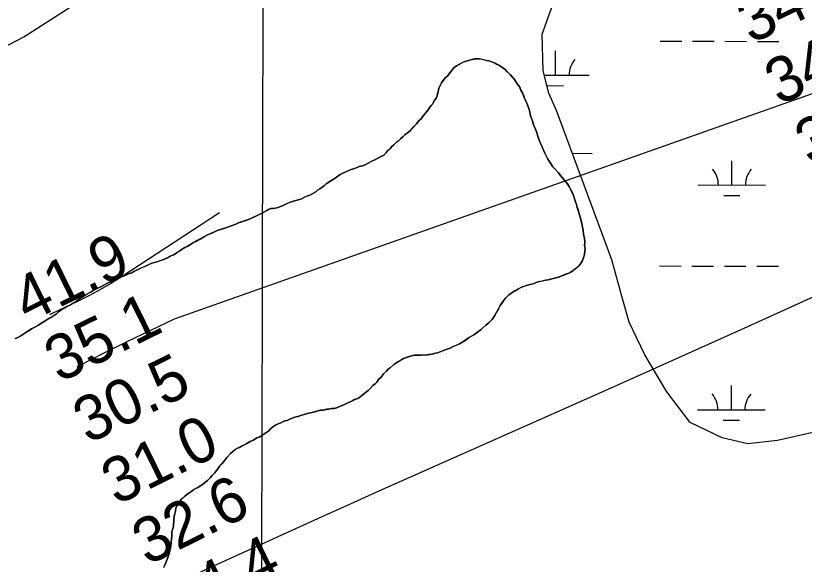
# Model space of a CAD drawing. Extents: x 3177385 to 3215275, y 903885 to 929304.
# Drawn here: x 3191697 to 3192865, y 914485 to 915297 of the extents above; entities that cross this region are included whole.
import ezdxf

# ---------------------------------------------------------------- set-up
doc = ezdxf.new("R2010")
doc.units = 0
for name, color, linetype in [('V-BORW-LINE', 7, 'Continuous'), ('V-GRID-MAJR', 7, 'Continuous'), ('V-RIVR-RANG', 7, 'Continuous'), ('V-SITE-VEGE', 7, 'Continuous'), ('V-TOPO-MAJR', 7, 'Continuous'), ('V-TOPO-MINR', 7, 'Continuous'), ('V-TOPO-SHOR', 7, 'Continuous'), ('V-WETL-SWMP', 7, 'Continuous')]:
    doc.layers.add(name, color=color, linetype=linetype)

msp = doc.modelspace()

# ---------------------------------------------------------------- linework, layer by layer
at = {"layer": 'V-BORW-LINE'}
for points in [[(3191709.1, 915265.3), (3191863.4, 915364.4)], [(3191587.4, 915201.6), (3191709.1, 915265.3)]]:
    msp.add_lwpolyline(points, dxfattribs=at)
at = {"layer": 'V-GRID-MAJR'}
msp.add_spline([(3192048.7, 909312.8), (3192063.7, 915372.6), (3192078.7, 921435.5), (3192093.7, 927498.5), (3192093.7, 927501.6)], degree=3, dxfattribs=at)
at = {"layer": 'V-SITE-VEGE'}
for points in [[(3192531.7, 914926.9), (3192534.5, 914931), (3192536, 914933.6), (3192538.5, 914940.1), (3192539.3, 914943.9), (3192540.3, 914952.6), (3192539.6, 914956.4), (3192539.7, 914961.4), (3192539.4, 914967.1), (3192538, 914973.2), (3192537.4, 914979.4), (3192536.3, 914983.6), (3192535.3, 914989.3), (3192532.5, 915000.4), (3192530.7, 915006.9), (3192528.2, 915014.2), (3192527.5, 915017.3), (3192526.1, 915021.5), (3192523.2, 915030.7), (3192519.2, 915039.2), (3192516.7, 915043.8), (3192512.2, 915050.4), (3192506.3, 915057.4), (3192503.3, 915060.5), (3192500.7, 915064), (3192495.5, 915070.2), (3192492.5, 915073.3), (3192489.9, 915076.8), (3192485.1, 915084.5), (3192480.4, 915093.4), (3192476, 915103.8), (3192473.1, 915110.3), (3192471.3, 915115.3), (3192467.7, 915126.4), (3192465.9, 915131), (3192464.1, 915135.3), (3192463.1, 915139.5), (3192459.4, 915148.7), (3192458.4, 915154.5), (3192457, 915159.4), (3192454.8, 915164.8), (3192452.3, 915170.6), (3192450.5, 915174.4), (3192447.9, 915181.4), (3192444.6, 915187.5), (3192443.6, 915191), (3192439.9, 915196), (3192435.8, 915202.2), (3192432.5, 915206.1), (3192429.1, 915209.6), (3192424.3, 915214.3), (3192422, 915217), (3192417.1, 915220.5), (3192413.4, 915222.9), (3192405.9, 915227.2), (3192397.9, 915230.1), (3192394.5, 915230.5), (3192383.9, 915233), (3192379.7, 915233.1), (3192376.6, 915232.8), (3192370.5, 915231.4), (3192366.3, 915230), (3192362.4, 915228.9), (3192358.6, 915227.5), (3192353.2, 915224.5), (3192349.7, 915222.3), (3192346.6, 915220.1), (3192343.9, 915217.1), (3192336.4, 915207.4), (3192333.7, 915205.5), (3192331.8, 915202.9), (3192327.8, 915197.3), (3192325.5, 915193.5), (3192324.3, 915190.5), (3192323.1, 915187.1), (3192322.6, 915184), (3192321, 915178), (3192319.7, 915174.9), (3192317.8, 915172.3), (3192314.6, 915167), (3192314.2, 915165.9), (3192312.7, 915164.4), (3192310.3, 915161.4), (3192308.7, 915158.8), (3192306.4, 915155.4), (3192304, 915152.4), (3192300.5, 915148.3), (3192297.4, 915144.2), (3192295, 915141.9), (3192292.3, 915138.9), (3192290.3, 915136.3), (3192281.8, 915127), (3192278.7, 915124.4), (3192275.9, 915122.5), (3192273.2, 915120.3), (3192270.9, 915118), (3192267, 915114.7), (3192264.3, 915112.1), (3192261.6, 915110.2), (3192256.9, 915105.4), (3192254.2, 915103.2)], [(3192254.2, 915103.2), (3192251.9, 915100.9), (3192242.1, 915090.5), (3192237.1, 915087.9), (3192233.2, 915086.1), (3192229.8, 915083.9), (3192224.4, 915081.3), (3192214.7, 915076.2), (3192210.9, 915074.7), (3192205.9, 915073.7), (3192202.8, 915072.2), (3192197.1, 915070.1), (3192192.5, 915068.6), (3192184.8, 915065.4), (3192181.7, 915063.5), (3192177.8, 915061.7), (3192172.4, 915058), (3192168.9, 915055.4), (3192166.2, 915053.6), (3192162.4, 915051.4), (3192157, 915047.7), (3192154.2, 915045.4), (3192147.3, 915040.3), (3192144.2, 915038.4), (3192141.5, 915036.2), (3192137.2, 915033.6), (3192132.6, 915031), (3192129.5, 915030.3), (3192124.9, 915028.2), (3192119.5, 915025.2), (3192115.3, 915024.2), (3192103.8, 915020.6), (3192096.1, 915017.3), (3192093.4, 915015.9), (3192089.2, 915014.4), (3192085.7, 915013), (3192081.5, 915011.9), (3192075, 915011.3), (3192071.7, 915010), (3192068.9, 915008.3)], [(3192068.9, 915008.3), (3192060.9, 915004.2), (3192057.7, 915002.4), (3192044.1, 914996.1), (3192034.7, 914992.6), (3192026.9, 914990), (3192023.1, 914988.2), (3192016.4, 914985.6), (3192012.3, 914984.4), (3192008.4, 914983), (3191997.1, 914979.4), (3191993.6, 914977.9), (3191985, 914974.1), (3191981.3, 914972.2), (3191960.6, 914960.9), (3191957.6, 914959.1), (3191953.7, 914956.4), (3191950.9, 914955), (3191947.5, 914953.6), (3191942.7, 914950.5), (3191939.9, 914948.4), (3191930.6, 914942.6), (3191926.1, 914941), (3191922.8, 914938.9), (3191913.6, 914934.7), (3191906.3, 914932.7), (3191902.9, 914931.5), (3191898.6, 914930.3), (3191894.3, 914928.7), (3191888.4, 914925.8), (3191881.6, 914922.8), (3191878.3, 914920.9), (3191875.3, 914919.5), (3191872.3, 914918.3), (3191869.1, 914916.4), (3191865.2, 914915), (3191861.1, 914913), (3191857.9, 914911.7), (3191850.3, 914908.5), (3191846.9, 914906.9), (3191841.7, 914904.2), (3191835.3, 914901.8), (3191832, 914900.3), (3191827.5, 914897.9), (3191823, 914895.6), (3191820, 914894), (3191812, 914890.1), (3191809, 914888.3), (3191800.1, 914883.3), (3191795.6, 914880), (3191792.3, 914878), (3191789.9, 914876.1), (3191785, 914872.8), (3191781.3, 914870.9), (3191778.5, 914868.9), (3191773.1, 914866.2), (3191766.8, 914862.9), (3191764, 914861.1), (3191760.6, 914858.6), (3191757.5, 914855.7), (3191749.5, 914850.3), (3191746.3, 914848.7), (3191742.2, 914846.2), (3191739.3, 914844.1), (3191734.6, 914841.2), (3191730.9, 914838.7), (3191724.7, 914835.5), (3191720.8, 914833.2), (3191712.1, 914827.8), (3191709.1, 914825.8), (3191704.6, 914823.1), (3191699.4, 914820.2), (3191696.2, 914818.8)], [(3192028.6, 914657.8), (3192031.7, 914659.7), (3192034.8, 914661.1), (3192039.4, 914663.7), (3192044.4, 914666.7), (3192049, 914668.5), (3192054.4, 914671.8), (3192057.5, 914673.2), (3192061.4, 914675.4), (3192064.5, 914677.3), (3192071.8, 914682.5), (3192074.5, 914685.5), (3192077.7, 914688.1), (3192081.9, 914690.6), (3192085.8, 914692.5), (3192088.8, 914693.5), (3192091.9, 914695.4), (3192095.8, 914697.2), (3192099.2, 914697.9), (3192104.2, 914700.1), (3192110.7, 914702.6), (3192115, 914703.6), (3192119.2, 914705.1), (3192125.7, 914706.9), (3192131.1, 914708.6), (3192136, 914709.7), (3192148.7, 914712.8), (3192152.5, 914713.1), (3192165.5, 914715.5), (3192169.3, 914715.5), (3192173.5, 914716.9), (3192178.9, 914719.4), (3192183.2, 914720.9), (3192187.8, 914723.1), (3192193.2, 914726), (3192196.3, 914727.1), (3192199, 914728.5), (3192203.9, 914730.3), (3192209.4, 914734), (3192214.4, 914738.5), (3192219.1, 914742.2), (3192221.8, 914744.8), (3192226.1, 914749.3), (3192229.6, 914751.9), (3192231.9, 914754.5), (3192234.6, 914758.3), (3192238.2, 914762), (3192241.7, 914766.5), (3192246, 914770.6), (3192248.7, 914773.6), (3192251.4, 914775.4), (3192257.2, 914780.3), (3192263, 914784.3), (3192271.5, 914789.5), (3192281.5, 914792.7), (3192287.6, 914794.1), (3192292.6, 914794.4), (3192297.5, 914794.3), (3192300.6, 914794.6), (3192304, 914794.5), (3192314, 914795.8), (3192317, 914796.9), (3192321.6, 914798), (3192325.5, 914799.4), (3192330.8, 914801.2), (3192335.8, 914803), (3192340.4, 914804.8), (3192345.1, 914807), (3192354.3, 914811), (3192364.3, 914817.2), (3192367.8, 914819.8), (3192375.6, 914824.6), (3192381, 914828.3), (3192386.4, 914832.4), (3192388.7, 914834.6), (3192393.4, 914838.7), (3192398.8, 914843.2), (3192402.7, 914847.3), (3192404.7, 914850.3), (3192407.1, 914854.1), (3192411.8, 914863.1), (3192414.6, 914867.6), (3192420.1, 914875.9), (3192422.4, 914878.5), (3192427.1, 914883.4), (3192432.1, 914887.1), (3192440.6, 914892.2), (3192446, 914894.8), (3192454.9, 914898), (3192458.7, 914899.1), (3192463.3, 914900.1), (3192466.8, 914901.2), (3192470.2, 914902.7), (3192481.7, 914905.1), (3192485.5, 914905.8), (3192495.1, 914908.2), (3192500.9, 914910), (3192516.2, 914915.8), (3192519.3, 914917.2), (3192522.4, 914919.5), (3192531.7, 914926.9)], [(3191916.6, 914480), (3191920.2, 914488.3), (3191923.8, 914499.2), (3191925.1, 914503), (3191925.9, 914506.8), (3191927.1, 914511), (3191927.3, 914517.5), (3191927.8, 914522.8), (3191928.2, 914526.6), (3191928.4, 914532.7), (3191929.6, 914537.6), (3191930.8, 914541.4), (3191931.4, 914550.5), (3191931.9, 914555.9), (3191933.6, 914563.4), (3191934.5, 914568.4), (3191936.1, 914571.8), (3191937.6, 914574.4), (3191940, 914577.4), (3191942.7, 914581.2), (3191947.4, 914585.6), (3191950.5, 914588.2), (3191956.3, 914592.3), (3191961, 914595.3), (3191967.1, 914598.6), (3191970.6, 914601.2), (3191973.7, 914603), (3191976.8, 914605.2), (3191981.4, 914608.9), (3191985, 914613), (3191988.1, 914616.4), (3191991.6, 914619.8), (3191994.3, 914623.5), (3191996.7, 914626.1), (3191998.6, 914629.1), (3192005.3, 914637), (3192009.6, 914643), (3192015.4, 914648.6), (3192018.9, 914651.6), (3192022.1, 914654.6), (3192025.5, 914656.8), (3192028.6, 914657.8)]]:
    msp.add_lwpolyline(points, dxfattribs=at)
at = {"layer": 'V-TOPO-MAJR'}
msp.add_lwpolyline([(3191998.7, 915005.2), (3191854.9, 914910.9), (3191839, 914901), (3191822.9, 914891.5), (3191806.4, 914882.6), (3191789.6, 914874.2), (3191751.1, 914855.8), (3191747.4, 914854.1)], dxfattribs=at)
at = {"layer": 'V-TOPO-MINR'}
for points in [[(3193910, 915545.9), (3193851.2, 915525.6), (3193792.7, 915504.9), (3193770.2, 915496.8), (3193700.5, 915471.5), (3193630.9, 915446.1), (3193561.3, 915420.5), (3193491.8, 915394.9), (3193380, 915353.4), (3193307.5, 915326.9), (3193234.9, 915301.1), (3193161.9, 915276), (3193088.8, 915251.4), (3192986.9, 915217.8), (3192964.6, 915210.7), (3192942.1, 915204.1), (3191931.7, 914847.6), (3191896.6, 914830.9), (3191861.6, 914813.9), (3191826.7, 914796.6), (3191792, 914779), (3191787.8, 914776.8)], [(3191639.2, 914323.2), (3191734.4, 914366.2), (3191829.6, 914409.4), (3191948.7, 914463.5), (3191984.3, 914479.6), (3192019.9, 914495.8), (3192055.5, 914512.1), (3192091.2, 914528.3), (3192106.5, 914535.2), (3192149.8, 914554.9), (3192193.1, 914574.4), (3192236.5, 914593.9), (3192279.9, 914613.2), (3192451.1, 914689.2), (3192533.6, 914725.9), (3192616.2, 914762.8), (3192698.6, 914799.8), (3192781.1, 914836.9), (3192889.7, 914885.9)]]:
    msp.add_lwpolyline(points, dxfattribs=at)
at = {"layer": 'V-TOPO-SHOR'}
for points in [[(3192075, 915011.3), (3192078.4, 915011.6), (3192081.5, 915011.9), (3192085.7, 915013), (3192089.2, 915014.4), (3192093.4, 915015.9), (3192096.1, 915017.3), (3192100.3, 915019.2), (3192103.8, 915020.6), (3192107.2, 915021.7), (3192111.8, 915023.1), (3192115.3, 915024.2), (3192119.5, 915025.2), (3192124.9, 915028.2), (3192129.5, 915030.3), (3192132.6, 915031), (3192137.2, 915033.6), (3192141.5, 915036.2), (3192144.2, 915038.4), (3192147.3, 915040.3), (3192154.2, 915045.4), (3192157, 915047.7), (3192162.4, 915051.4), (3192166.2, 915053.6), (3192168.9, 915055.4), (3192172.4, 915058), (3192177.8, 915061.7), (3192181.7, 915063.5), (3192184.8, 915065.4), (3192188.2, 915066.8), (3192192.5, 915068.6), (3192197.1, 915070.1), (3192202.8, 915072.2), (3192205.9, 915073.7), (3192210.9, 915074.7), (3192214.7, 915076.2), (3192219, 915078.4), (3192224.4, 915081.3), (3192229.8, 915083.9), (3192233.2, 915086.1), (3192237.1, 915087.9), (3192242.1, 915090.5), (3192246, 915094.6), (3192248.3, 915097.2), (3192251.9, 915100.9), (3192254.2, 915103.2), (3192256.9, 915105.4), (3192261.6, 915110.2), (3192264.3, 915112.1), (3192267, 915114.7), (3192270.9, 915118), (3192273.2, 915120.3), (3192275.9, 915122.5), (3192278.7, 915124.4), (3192281.8, 915127), (3192284.1, 915129.6), (3192286.8, 915132.6), (3192290.3, 915136.3), (3192292.3, 915138.9), (3192295, 915141.9), (3192297.4, 915144.2), (3192300.5, 915148.3), (3192304, 915152.4), (3192306.4, 915155.4), (3192308.7, 915158.8), (3192310.3, 915161.4), (3192312.7, 915164.4), (3192314.2, 915165.9), (3192314.6, 915167), (3192316.2, 915169.7), (3192317.8, 915172.3), (3192319.7, 915174.9), (3192321, 915178), (3192321.8, 915181), (3192322.6, 915184), (3192323.1, 915187.1), (3192324.3, 915190.5), (3192325.5, 915193.5), (3192327.8, 915197.3), (3192331.8, 915202.9), (3192333.7, 915205.5), (3192336.4, 915207.4), (3192339.6, 915211.5), (3192341.9, 915214.5), (3192343.9, 915217.1), (3192346.6, 915220.1), (3192349.7, 915222.3), (3192353.2, 915224.5), (3192355.9, 915226), (3192358.6, 915227.5), (3192362.4, 915228.9), (3192366.3, 915230), (3192370.5, 915231.4), (3192373.6, 915232.1), (3192376.6, 915232.8), (3192379.7, 915233.1), (3192383.9, 915233), (3192387.3, 915232.2), (3192391.1, 915231.3), (3192394.5, 915230.5), (3192397.9, 915230.1)], [(3192397.9, 915230.1), (3192402.4, 915228.4), (3192405.9, 915227.2), (3192409.2, 915225.2), (3192413.4, 915222.9), (3192417.1, 915220.5), (3192422, 915217), (3192424.3, 915214.3), (3192429.1, 915209.6), (3192432.5, 915206.1), (3192435.8, 915202.2), (3192439.9, 915196), (3192443.6, 915191), (3192444.6, 915187.5), (3192447.9, 915181.4), (3192449.4, 915177.5), (3192450.5, 915174.4), (3192452.3, 915170.6), (3192454.8, 915164.8), (3192457, 915159.4), (3192458.4, 915154.5), (3192459.4, 915148.7), (3192463.1, 915139.5), (3192464.1, 915135.3), (3192465.9, 915131), (3192467.7, 915126.4), (3192471.3, 915115.3), (3192473.1, 915110.3), (3192476, 915103.8), (3192478.6, 915097.6), (3192480.4, 915093.4), (3192481.8, 915090.7), (3192485.1, 915084.5), (3192489.9, 915076.8), (3192492.5, 915073.3), (3192495.5, 915070.2), (3192500.7, 915064), (3192503.3, 915060.5), (3192506.3, 915057.4), (3192509.3, 915053.9), (3192512.2, 915050.4), (3192514.1, 915047.7), (3192516.7, 915043.8), (3192519.2, 915039.2), (3192521.4, 915034.6), (3192523.2, 915030.7), (3192524.3, 915027.3), (3192526.1, 915021.5), (3192527.5, 915017.3), (3192528.2, 915014.2), (3192529.3, 915011.2), (3192530.7, 915006.9), (3192532.5, 915000.4), (3192534.3, 914993.5), (3192535.3, 914989.3), (3192536.3, 914983.6), (3192537.4, 914979.4), (3192538, 914973.2), (3192539.4, 914967.1), (3192539.7, 914961.4), (3192539.6, 914956.4), (3192540.3, 914952.6), (3192539.8, 914947.7), (3192539.3, 914943.9), (3192538.5, 914940.1), (3192536, 914933.6), (3192534.5, 914931), (3192531.7, 914926.9), (3192527.1, 914923.2), (3192522.4, 914919.5), (3192519.3, 914917.2), (3192516.2, 914915.8), (3192510.5, 914913.6), (3192500.9, 914910), (3192495.1, 914908.2), (3192490.9, 914907.2), (3192485.5, 914905.8), (3192481.7, 914905.1), (3192476.7, 914904), (3192470.2, 914902.7), (3192466.8, 914901.2), (3192463.3, 914900.1), (3192458.7, 914899.1), (3192454.9, 914898), (3192451, 914896.6), (3192446, 914894.8), (3192440.6, 914892.2), (3192436.4, 914889.7), (3192432.1, 914887.1), (3192427.1, 914883.4), (3192422.4, 914878.5), (3192420.1, 914875.9), (3192417.3, 914871.8), (3192414.6, 914867.6), (3192411.8, 914863.1), (3192408.6, 914857.1), (3192407.1, 914854.1), (3192404.7, 914850.3), (3192402.7, 914847.3), (3192398.8, 914843.2), (3192393.4, 914838.7)], [(3191985, 914974.1), (3191989.5, 914976.1), (3191993.6, 914977.9), (3191997.1, 914979.4), (3192002, 914981), (3192005.2, 914982), (3192008.4, 914983), (3192012.3, 914984.4), (3192016.4, 914985.6), (3192023.1, 914988.2), (3192026.9, 914990), (3192030.4, 914991.2), (3192034.7, 914992.6), (3192039.2, 914994.2), (3192044.1, 914996.1), (3192047.1, 914997.5), (3192051.5, 914999.5), (3192054.7, 915001), (3192057.7, 915002.4), (3192060.9, 915004.2), (3192063.7, 915005.7), (3192068.9, 915008.3), (3192071.7, 915010), (3192075, 915011.3)], [(3191696.2, 914818.8), (3191699.4, 914820.2), (3191704.6, 914823.1), (3191709.1, 914825.8), (3191712.1, 914827.8), (3191715.8, 914830.1), (3191720.8, 914833.2), (3191724.7, 914835.5), (3191730.9, 914838.7), (3191734.6, 914841.2), (3191739.3, 914844.1), (3191742.2, 914846.2), (3191746.3, 914848.7), (3191749.5, 914850.3), (3191752.5, 914852.4), (3191757.5, 914855.7), (3191760.6, 914858.6), (3191764, 914861.1), (3191766.8, 914862.9), (3191770.1, 914864.6), (3191773.1, 914866.2), (3191778.5, 914868.9), (3191781.3, 914870.9), (3191785, 914872.8), (3191789.9, 914876.1), (3191792.3, 914878), (3191795.6, 914880), (3191800.1, 914883.3), (3191804.2, 914885.6), (3191809, 914888.3), (3191812, 914890.1), (3191820, 914894), (3191823, 914895.6), (3191827.5, 914897.9), (3191832, 914900.3), (3191835.3, 914901.8), (3191838.5, 914903), (3191841.7, 914904.2), (3191846.9, 914906.9), (3191850.3, 914908.5), (3191854, 914910.1), (3191857.9, 914911.7), (3191861.1, 914913), (3191865.2, 914915), (3191869.1, 914916.4), (3191872.3, 914918.3), (3191875.3, 914919.5), (3191878.3, 914920.9), (3191881.6, 914922.8), (3191885.2, 914924.4), (3191888.4, 914925.8), (3191891.5, 914927.2), (3191894.3, 914928.7), (3191898.6, 914930.3), (3191902.9, 914931.5), (3191906.3, 914932.7), (3191909.9, 914933.7), (3191913.6, 914934.7), (3191917.5, 914936.5), (3191922.8, 914938.9), (3191926.1, 914941), (3191930.6, 914942.6), (3191936.2, 914946.1), (3191939.9, 914948.4), (3191942.7, 914950.5), (3191947.5, 914953.6), (3191950.9, 914955), (3191953.7, 914956.4), (3191957.6, 914959.1), (3191960.6, 914960.9), (3191963.7, 914962.6), (3191966.7, 914964.2), (3191970.1, 914966.1), (3191976.8, 914969.8), (3191981.3, 914972.2), (3191985, 914974.1)], [(3192393.4, 914838.7), (3192388.7, 914834.6), (3192386.4, 914832.4), (3192381, 914828.3), (3192375.6, 914824.6), (3192372.1, 914822.4), (3192367.8, 914819.8), (3192364.3, 914817.3), (3192360.1, 914814.7), (3192354.3, 914811), (3192349.3, 914808.8), (3192345.1, 914807), (3192340.4, 914804.8), (3192335.8, 914803), (3192330.8, 914801.2), (3192325.5, 914799.4), (3192321.6, 914798), (3192317, 914796.9), (3192314, 914795.8), (3192309, 914795.2), (3192304, 914794.5), (3192300.6, 914794.6), (3192297.5, 914794.3), (3192292.6, 914794.4), (3192287.6, 914794.1), (3192281.5, 914792.7), (3192276.9, 914791.3), (3192271.5, 914789.5), (3192267.3, 914786.9), (3192263, 914784.3), (3192257.2, 914780.3), (3192251.4, 914775.4), (3192248.7, 914773.6), (3192246, 914770.6), (3192241.7, 914766.5), (3192238.2, 914762), (3192234.6, 914758.3), (3192231.9, 914754.5), (3192229.6, 914751.9), (3192226.1, 914749.3), (3192221.8, 914744.8), (3192219.1, 914742.2), (3192214.4, 914738.5), (3192209.4, 914734), (3192206.7, 914732.2), (3192203.9, 914730.3), (3192199, 914728.5), (3192196.3, 914727.1), (3192193.2, 914726), (3192187.8, 914723.1), (3192183.2, 914720.9), (3192178.9, 914719.4), (3192173.5, 914716.9), (3192169.3, 914715.5), (3192165.5, 914715.5), (3192162.1, 914714.8), (3192157.9, 914714.2), (3192152.5, 914713.1), (3192148.7, 914712.8), (3192144.5, 914711.8), (3192136, 914709.7), (3192131.1, 914708.6), (3192125.7, 914706.9), (3192119.2, 914705.1), (3192115, 914703.6), (3192110.7, 914702.6), (3192104.2, 914700.1), (3192099.2, 914697.9), (3192095.8, 914697.2), (3192091.9, 914695.4), (3192088.8, 914693.5), (3192085.8, 914692.5), (3192081.9, 914690.6), (3192077.7, 914688.1), (3192074.5, 914685.5), (3192071.8, 914682.5), (3192064.5, 914677.3), (3192061.4, 914675.4), (3192057.5, 914673.2), (3192054.4, 914671.8), (3192049, 914668.5), (3192044.4, 914666.7), (3192039.4, 914663.7), (3192034.8, 914661.1), (3192031.7, 914659.7), (3192028.6, 914657.8), (3192025.5, 914656.8), (3192022.1, 914654.6), (3192018.9, 914651.6), (3192015.4, 914648.6), (3192009.6, 914643), (3192007.3, 914639.6), (3192005.3, 914637), (3192002.2, 914633.3), (3191998.6, 914629.1), (3191996.7, 914626.1), (3191994.3, 914623.5), (3191991.6, 914619.8), (3191988.1, 914616.4), (3191985, 914613), (3191981.4, 914608.9)], [(3191981.4, 914608.9), (3191976.8, 914605.2), (3191973.7, 914603), (3191970.6, 914601.2), (3191967.1, 914598.6), (3191964.4, 914597.1), (3191961, 914595.3), (3191956.3, 914592.3), (3191953.2, 914590.1), (3191950.5, 914588.2), (3191947.4, 914585.6), (3191945.1, 914583.4), (3191942.7, 914581.2), (3191940, 914577.4), (3191937.6, 914574.4), (3191936.1, 914571.8), (3191934.5, 914568.4), (3191933.6, 914563.4), (3191932.8, 914559.7), (3191931.9, 914555.9), (3191931.4, 914550.5), (3191930.8, 914541.4), (3191929.6, 914537.6), (3191928.4, 914532.7), (3191928.2, 914526.6), (3191927.8, 914522.8), (3191927.3, 914517.5), (3191927.1, 914511), (3191925.9, 914506.8), (3191925.1, 914503), (3191923.8, 914499.2), (3191921.8, 914493.2), (3191920.2, 914488.3), (3191918.2, 914483.7)]]:
    msp.add_lwpolyline(points, dxfattribs=at)
at = {"layer": 'V-WETL-SWMP'}
for p, q in [((3192651.3, 915259), (3192683.3, 915258.9)), ((3192699.3, 915258.9), (3192731.3, 915258.8)), ((3192747.3, 915258.8), (3192779.3, 915258.7)), ((3192795.3, 915258.6), (3192827.3, 915258.6)), ((3192496.5, 915208.6), (3192496.6, 915244.6)), ((3192479.7, 915208.6), (3192546.5, 915208.5)), ((3192484.5, 915193.2), (3192508.5, 915193.1)), ((3192521.4, 915093.1), (3192550.9, 915093)), ((3192757.6, 915046.1), (3192757.7, 915082.1)), ((3192707.6, 915046.2), (3192807.6, 915046)), ((3192745.6, 915030.7), (3192769.6, 915030.7)), ((3192650.5, 914926.3), (3192682.5, 914926.2)), ((3192698.5, 914926.2), (3192730.5, 914926.1)), ((3192746.5, 914926.1), (3192778.5, 914926)), ((3192794.5, 914926), (3192826.5, 914925.9)), ((3192756.8, 914713.5), (3192756.9, 914749.5)), ((3192706.8, 914713.6), (3192806.8, 914713.3)), ((3192744.8, 914698.1), (3192768.8, 914698))]:
    msp.add_line(p, q, dxfattribs=at)
msp.add_lwpolyline([(3194937.3, 915221.8), (3194855.7, 915199.6), (3194745.5, 915161.5), (3194339, 915087), (3194244, 915054.5), (3194129.1, 915029.2), (3194060.9, 915014.9), (3193474.3, 914837.1), (3193346.6, 914786.2), (3192825, 914667.9), (3192781, 914662.9), (3192743.3, 914672.2), (3192696, 914694.7), (3192661.2, 914740), (3192628.7, 914794.8), (3192605.7, 914843.4), (3192596.1, 914876.3), (3192580, 914935.2), (3192498, 915156.2), (3192486.8, 915182), (3192478, 915215), (3192476.9, 915269.2), (3192492.4, 915313.2)], dxfattribs=at)
for centre, start, end in [((3192551.8, 915208.9), 139.0948, 180.6385), ((3192702.4, 915046.7), 359.0948, 40.6385), ((3192812.8, 915046.5), 139.0948, 180.6385), ((3192701.6, 914714.1), 359.0948, 40.6385), ((3192812.1, 914713.8), 139.0948, 180.6385)]:
    msp.add_arc(centre, 35.2, start, end, dxfattribs=at)

# ---------------------------------------------------------------- texts
at = {"layer": 'V-RIVR-RANG'}
for s, rotation, p in [('34.4', 25.4783, (3192786.1, 915254.3)), ('34.6', 25.4783, (3192827.6, 915163.3)), ('33.4', 25.4783, (3192872.5, 915074)), ('41.9', 26.3283, (3191715, 914841.2)), ('35.1', 26.3283, (3191761.9, 914752.8)), ('30.5', 26.3283, (3191804.4, 914662.3)), ('31.0', 26.3283, (3191846.3, 914571.5)), ('32.6', 26.3283, (3191891.9, 914482.4)), ('34.4', 26.3283, (3191938.1, 914393.7))]:
    msp.add_text(s, height=67, rotation=rotation, dxfattribs=at).set_placement(p)

doc.saveas('drawing.dxf')
